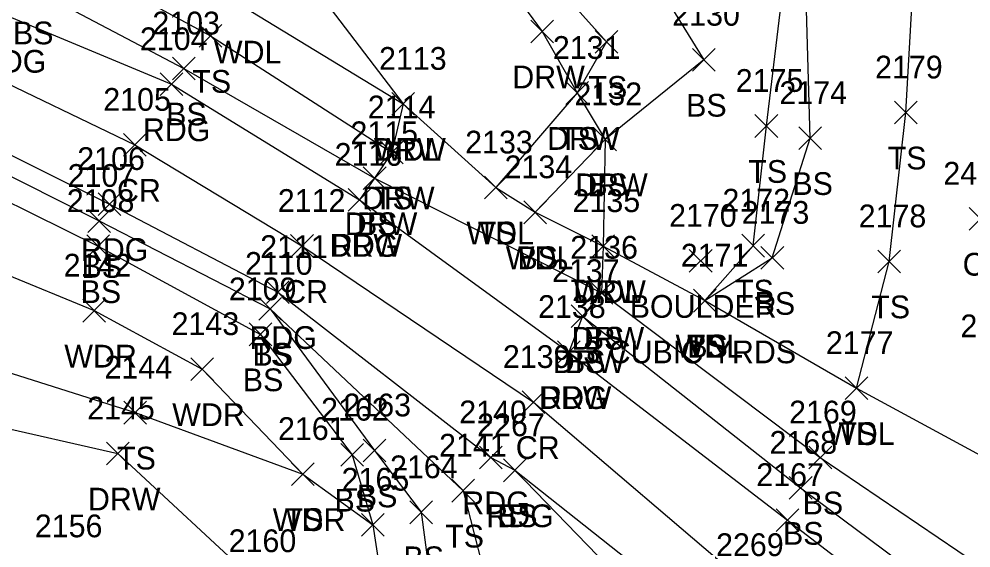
# Model space of a CAD drawing. Extents: x 1512665 to 1513714, y 110636 to 112816.
# Drawn here: x 1512914.5 to 1512998.3, y 110786.6 to 110833.1 of the extents above; entities that cross this region are included whole.
import ezdxf

# ---------------------------------------------------------------- set-up
doc = ezdxf.new("R2010")
doc.units = 0
for name, color, linetype in [('L_A', 7, 'Continuous'), ('L_C', 7, 'Continuous'), ('L_I', 7, 'Continuous'), ('L_TIC', 7, 'Continuous'), ('LAWA', 7, 'Continuous'), ('LELB', 7, 'Continuous'), ('P_A', 7, 'Continuous'), ('P_I', 7, 'Continuous'), ('P_TIC', 7, 'Continuous'), ('PEU', 7, 'Continuous'), ('PRC', 7, 'Continuous'), ('R_A', 7, 'Continuous'), ('R_I', 7, 'Continuous'), ('R_TIC', 7, 'Continuous'), ('RDW', 7, 'Continuous')]:
    doc.layers.add(name, color=color, linetype=linetype)

msp = doc.modelspace()

# ---------------------------------------------------------------- linework, layer by layer
at = {"layer": 'L_TIC'}
for points in [[(1512930.348, 110830.636), (1512932.348, 110832.636)], [(1512932.348, 110830.636), (1512930.348, 110832.636)], [(1512965.207, 110830.108), (1512967.207, 110832.108)], [(1512967.207, 110830.108), (1512965.207, 110832.108)], [(1512973.771, 110828.535), (1512975.771, 110830.535)], [(1512975.771, 110828.535), (1512973.771, 110830.535)], [(1512928.014, 110827.768), (1512930.014, 110829.768)], [(1512930.014, 110827.768), (1512928.014, 110829.768)], [(1512962.612, 110825.617), (1512964.612, 110827.617)], [(1512964.612, 110825.617), (1512962.612, 110827.617)], [(1512947.315, 110824.655), (1512949.315, 110826.655)], [(1512949.315, 110824.655), (1512947.315, 110826.655)], [(1512991.538, 110823.894), (1512993.538, 110825.894)], [(1512993.538, 110823.894), (1512991.538, 110825.894)], [(1512979.271, 110822.714), (1512981.271, 110824.714)], [(1512981.271, 110822.714), (1512979.271, 110824.714)], [(1512965.081, 110821.54), (1512967.081, 110823.54)], [(1512967.081, 110821.54), (1512965.081, 110823.54)], [(1512983.116, 110821.649), (1512985.116, 110823.649)], [(1512985.116, 110821.649), (1512983.116, 110823.649)], [(1512946.325, 110820.384), (1512948.325, 110822.384)], [(1512948.325, 110820.384), (1512946.325, 110822.384)], [(1512944.804, 110818.115), (1512946.804, 110820.115)], [(1512946.804, 110818.115), (1512944.804, 110820.115)], [(1512955.461, 110817.296), (1512957.461, 110819.296)], [(1512957.461, 110817.296), (1512955.461, 110819.296)], [(1512955.461, 110817.296), (1512957.461, 110819.296)], [(1512957.461, 110817.296), (1512955.461, 110819.296)], [(1512958.925, 110815.123), (1512960.925, 110817.123)], [(1512960.925, 110815.123), (1512958.925, 110817.123)], [(1512958.925, 110815.123), (1512960.925, 110817.123)], [(1512960.925, 110815.123), (1512958.925, 110817.123)], [(1512998.104, 110814.556), (1513000.104, 110816.556)], [(1513000.104, 110814.556), (1512998.104, 110816.556)], [(1512920.56, 110814.361), (1512922.56, 110816.361)], [(1512922.56, 110814.361), (1512920.56, 110816.361)], [(1512920.486, 110812.143), (1512922.486, 110814.143)], [(1512922.486, 110812.143), (1512920.486, 110814.143)], [(1512964.912, 110812.145), (1512966.912, 110814.145)], [(1512966.912, 110812.145), (1512964.912, 110814.145)], [(1512978.1, 110812.189), (1512980.1, 110814.189)], [(1512980.1, 110812.189), (1512978.1, 110814.189)], [(1512979.796, 110811.112), (1512981.796, 110813.112)], [(1512981.796, 110811.112), (1512979.796, 110813.112)], [(1512973.492, 110810.848), (1512975.492, 110812.848)], [(1512975.492, 110810.848), (1512973.492, 110812.848)], [(1512990.089, 110810.803), (1512992.089, 110812.803)], [(1512992.089, 110810.803), (1512990.089, 110812.803)], [(1512964.768, 110808.049), (1512966.768, 110810.049)], [(1512966.768, 110808.049), (1512964.768, 110810.049)], [(1512964.768, 110808.049), (1512966.768, 110810.049)], [(1512966.768, 110808.049), (1512964.768, 110810.049)], [(1512973.869, 110807.354), (1512975.869, 110809.354)], [(1512975.869, 110807.354), (1512973.869, 110809.354)], [(1512973.869, 110807.354), (1512975.869, 110809.354)], [(1512975.869, 110807.354), (1512973.869, 110809.354)], [(1512973.869, 110807.354), (1512975.869, 110809.354)], [(1512975.869, 110807.354), (1512973.869, 110809.354)], [(1512920.132, 110806.474), (1512922.132, 110808.474)], [(1512922.132, 110806.474), (1512920.132, 110808.474)], [(1512935.611, 110806.627), (1512937.611, 110808.627)], [(1512937.611, 110806.627), (1512935.611, 110808.627)], [(1512935.611, 110806.627), (1512937.611, 110808.627)], [(1512937.611, 110806.627), (1512935.611, 110808.627)], [(1512963.105, 110805.986), (1512965.105, 110807.986)], [(1512965.105, 110805.986), (1512963.105, 110807.986)], [(1512934.759, 110804.391), (1512936.759, 110806.391)], [(1512936.759, 110804.391), (1512934.759, 110806.391)], [(1512929.627, 110801.326), (1512931.627, 110803.326)], [(1512931.627, 110801.326), (1512929.627, 110803.326)], [(1512987.199, 110799.659), (1512989.199, 110801.659)], [(1512989.199, 110799.659), (1512987.199, 110801.659)], [(1512987.199, 110799.659), (1512989.199, 110801.659)], [(1512989.199, 110799.659), (1512987.199, 110801.659)], [(1512923.724, 110797.505), (1512925.724, 110799.505)], [(1512925.724, 110797.505), (1512923.724, 110799.505)], [(1512942.83, 110793.805), (1512944.83, 110795.805)], [(1512944.83, 110793.805), (1512942.83, 110795.805)], [(1512944.797, 110794.178), (1512946.797, 110796.178)], [(1512946.797, 110794.178), (1512944.797, 110796.178)], [(1512984.021, 110793.556), (1512986.021, 110795.556)], [(1512986.021, 110793.556), (1512984.021, 110795.556)], [(1512938.473, 110792.102), (1512940.473, 110794.102)], [(1512940.473, 110792.102), (1512938.473, 110794.102)], [(1512938.473, 110792.102), (1512940.473, 110794.102)], [(1512940.473, 110792.102), (1512938.473, 110794.102)], [(1512957.132, 110792.433), (1512959.132, 110794.433)], [(1512959.132, 110792.433), (1512957.132, 110794.433)], [(1512952.599, 110790.643), (1512954.599, 110792.643)], [(1512954.599, 110790.643), (1512952.599, 110792.643)], [(1512982.29, 110790.889), (1512984.29, 110792.889)], [(1512984.29, 110790.889), (1512982.29, 110792.889)], [(1512948.896, 110788.739), (1512950.896, 110790.739)], [(1512950.896, 110788.739), (1512948.896, 110790.739)], [(1512944.641, 110787.646), (1512946.641, 110789.646)], [(1512946.641, 110787.646), (1512944.641, 110789.646)], [(1512944.641, 110787.646), (1512946.641, 110789.646)], [(1512946.641, 110787.646), (1512944.641, 110789.646)]]:
    msp.add_lwpolyline(points, dxfattribs=at)
at = {"layer": 'LAWA'}
for points in [[(1512901.813, 110849.485), (1512918.081, 110842.567), (1512934.241, 110834.213), (1512948.315, 110825.655), (1512956.461, 110818.296), (1512959.925, 110816.123), (1512965.912, 110813.145), (1512974.869, 110808.354), (1512988.199, 110800.659), (1513000.869, 110793.798)], [(1512904.855, 110814.165), (1512921.132, 110807.474), (1512930.627, 110802.326), (1512939.473, 110793.102), (1512945.641, 110788.646), (1512946.819, 110780.951), (1512948.89, 110763.758), (1512946.989, 110749.434), (1512944.293, 110735.419), (1512940.962, 110714.938), (1512937.713, 110700.214), (1512950.792, 110688.786), (1512957.118, 110668.558), (1512971.82, 110659.404), (1512987.484, 110651.003), (1512993.751, 110649.548)]]:
    msp.add_lwpolyline(points, dxfattribs=at)
at = {"layer": 'LELB'}
for points in [[(1512867.091, 110954.959), (1512866.028, 110951.273), (1512867.897, 110945.243), (1512874.787, 110940.291), (1512895.063, 110927.72), (1512902.508, 110913.749), (1512928.484, 110897.044), (1512945.574, 110871.654), (1512953.444, 110855.33), (1512967.722, 110840.945), (1512974.771, 110829.535), (1512966.081, 110822.54), (1512959.925, 110816.123)], [(1512974.869, 110808.354), (1512980.796, 110812.112), (1512984.116, 110822.649), (1512983.374, 110849.355), (1512977.752, 110867.951), (1512973.997, 110889.114), (1512962.102, 110907.231), (1512950.876, 110925.19), (1512946.24, 110943.899), (1512941.465, 110952.585)], [(1512721.894, 110948.789), (1512722.497, 110942.68), (1512730.744, 110933.358), (1512741.905, 110924.629), (1512760.327, 110918.9), (1512788.256, 110897.799), (1512812.95, 110889.365), (1512823.675, 110884.08), (1512829.426, 110887.292), (1512828.602, 110891.881), (1512837.516, 110889.389), (1512842.176, 110886.401), (1512840.963, 110881.395), (1512842.492, 110877.537), (1512859.927, 110867.233), (1512885.327, 110852.839), (1512900.342, 110845.897), (1512916.833, 110839.511), (1512931.348, 110831.636), (1512947.325, 110821.384)], [(1512974.869, 110808.354), (1512979.1, 110813.189), (1512980.271, 110823.714), (1512983.374, 110849.355), (1512972.278, 110865.98), (1512966.818, 110886.579), (1512961.43, 110907.503), (1512945.779, 110917.038), (1512935.312, 110927.852), (1512933.427, 110939.129), (1512946.24, 110943.899), (1512951.888, 110947.414), (1512965.517, 110949.054), (1512967.677, 110937.89)], [(1512700.679, 110948.394), (1512702.883, 110937.76), (1512707.699, 110928.255), (1512715.725, 110919.825), (1512729.364, 110912.396), (1512733.114, 110910.816), (1512749.564, 110901.484), (1512765.39, 110894.395), (1512774.129, 110890.874), (1512779.73, 110888.581), (1512784.329, 110885.95), (1512807.054, 110874.728), (1512832.029, 110862.151), (1512849.873, 110852.9), (1512877.541, 110837.789), (1512892.067, 110830.383), (1512907.918, 110822.224), (1512921.56, 110815.361), (1512936.611, 110807.627), (1512945.797, 110795.178), (1512949.896, 110789.739), (1512950.992, 110781.568)], [(1512988.199, 110800.659), (1512991.089, 110811.803), (1512992.538, 110824.894), (1512993.987, 110850.149), (1512990.903, 110870.015), (1512992.225, 110882.229), (1512991.179, 110906.022), (1512982.382, 110920.046), (1512967.677, 110937.89)], [(1512899.968, 110905.165), (1512920.267, 110889.921), (1512938.022, 110866.04), (1512947.184, 110852.269), (1512966.207, 110831.108), (1512963.612, 110826.617), (1512956.461, 110818.296)], [(1512855.917, 110864.835), (1512884.122, 110850.682), (1512899.11, 110843.508), (1512915.531, 110835.895), (1512929.014, 110828.768), (1512945.804, 110819.115), (1512965.768, 110809.049)], [(1512832.029, 110862.151), (1512848.907, 110851.825), (1512876.28, 110836.219), (1512891.615, 110828.789), (1512906.871, 110820.366), (1512921.486, 110813.143), (1512935.759, 110805.391), (1512943.83, 110794.805), (1512945.641, 110788.646)], [(1512869.571, 110820.499), (1512887.31, 110807.394), (1512901.849, 110805.769), (1512924.724, 110798.505), (1512939.473, 110793.102)], [(1512965.768, 110809.049), (1512985.021, 110794.556), (1513002.316, 110782.838), (1513012.084, 110779.37), (1513025.948, 110772.452), (1513031.778, 110776.166)], [(1512936.611, 110807.627), (1512953.599, 110791.643), (1512956.195, 110781.418), (1512968.46, 110770.893), (1512974.971, 110752.732), (1512977.394, 110741.958), (1512974.26, 110721.428)], [(1512964.105, 110806.986), (1512983.29, 110791.889), (1512999.323, 110779.951), (1513012.212, 110774.48), (1513024.663, 110768.294), (1513032.242, 110771.906), (1513035.849, 110774.486)], [(1512958.132, 110793.433), (1512973.652, 110777.453), (1512981.607, 110755.641), (1512996.294, 110746.637), (1513006.992, 110744.376), (1513016.029, 110743.308), (1513026.953, 110745.673), (1513036.177, 110748.289)]]:
    msp.add_lwpolyline(points, dxfattribs=at)
at = {"layer": 'P_TIC'}
for points in [[(1512926.92, 110826.382), (1512928.92, 110828.382)], [(1512928.92, 110826.382), (1512926.92, 110828.382)], [(1512923.695, 110821.052), (1512925.695, 110823.052)], [(1512925.695, 110821.052), (1512923.695, 110823.052)], [(1512943.462, 110816.212), (1512945.462, 110818.212)], [(1512945.462, 110816.212), (1512943.462, 110818.212)], [(1512921.462, 110815.848), (1512923.462, 110817.848)], [(1512923.462, 110815.848), (1512921.462, 110817.848)], [(1512938.408, 110812.161), (1512940.408, 110814.161)], [(1512940.408, 110812.161), (1512938.408, 110814.161)], [(1512936.29, 110808.107), (1512938.29, 110810.107)], [(1512938.29, 110808.107), (1512936.29, 110810.107)], [(1512961.879, 110802.833), (1512963.879, 110804.833)], [(1512963.879, 110802.833), (1512961.879, 110804.833)], [(1512958.787, 110798.435), (1512960.787, 110800.435)], [(1512960.787, 110798.435), (1512958.787, 110800.435)], [(1512955.028, 110793.571), (1512957.028, 110795.571)], [(1512957.028, 110793.571), (1512955.028, 110795.571)], [(1512957.132, 110792.433), (1512959.132, 110794.433)], [(1512959.132, 110792.433), (1512957.132, 110794.433)], [(1512981.126, 110788.052), (1512983.126, 110790.052)], [(1512983.126, 110788.052), (1512981.126, 110790.052)]]:
    msp.add_lwpolyline(points, dxfattribs=at)
at = {"layer": 'PEU'}
for points in [[(1512701.918, 111049.687), (1512700.272, 111027.695), (1512701.575, 110993.777), (1512707.634, 110973.739), (1512708.973, 110956.468), (1512713.567, 110946.899), (1512719.219, 110936.541), (1512726.895, 110929.376), (1512741.614, 110919.596), (1512758.159, 110912.379), (1512787.354, 110896.005), (1512813.053, 110887.984), (1512838.367, 110874.777), (1512855.917, 110864.835), (1512882.817, 110848.349), (1512898.24, 110841.366), (1512913.486, 110833.402), (1512927.92, 110827.382), (1512944.462, 110817.212), (1512962.879, 110803.833), (1512982.126, 110789.052), (1512997.253, 110777.445), (1513011.324, 110770.561), (1513024.004, 110765.991)], [(1512908.545, 110823.763), (1512922.462, 110816.848), (1512937.29, 110809.107), (1512956.028, 110794.571), (1512958.132, 110793.433), (1512975.798, 110779.469), (1512988.794, 110763.009), (1513002.098, 110756.133), (1513012.974, 110751.731), (1513022.336, 110752.03), (1513042.715, 110756.056), (1513045.977, 110758.546), (1513043.773, 110764.486), (1513041.72, 110768.766), (1513036.521, 110767.718), (1513024.004, 110765.991)]]:
    msp.add_lwpolyline(points, dxfattribs=at)
at = {"layer": 'PRC'}
msp.add_lwpolyline([(1512910.919, 110828.697), (1512924.695, 110822.052), (1512939.408, 110813.161), (1512959.787, 110799.435), (1512979.162, 110782.894), (1512994.968, 110767.907), (1513005.499, 110762.392), (1513013.716, 110758.318), (1513024.25, 110758.228), (1513034.128, 110760.688), (1513043.773, 110764.486)], dxfattribs=at)
at = {"layer": 'R_TIC'}
for points in [[(1512959.543, 110831.025), (1512961.543, 110833.025)], [(1512961.543, 110831.025), (1512959.543, 110833.025)], [(1512962.612, 110825.617), (1512964.612, 110827.617)], [(1512964.612, 110825.617), (1512962.612, 110827.617)], [(1512947.315, 110824.655), (1512949.315, 110826.655)], [(1512949.315, 110824.655), (1512947.315, 110826.655)], [(1512965.081, 110821.54), (1512967.081, 110823.54)], [(1512967.081, 110821.54), (1512965.081, 110823.54)], [(1512946.325, 110820.384), (1512948.325, 110822.384)], [(1512948.325, 110820.384), (1512946.325, 110822.384)], [(1512944.804, 110818.115), (1512946.804, 110820.115)], [(1512946.804, 110818.115), (1512944.804, 110820.115)], [(1512943.462, 110816.212), (1512945.462, 110818.212)], [(1512945.462, 110816.212), (1512943.462, 110818.212)], [(1512964.912, 110812.145), (1512966.912, 110814.145)], [(1512966.912, 110812.145), (1512964.912, 110814.145)], [(1512964.768, 110808.049), (1512966.768, 110810.049)], [(1512966.768, 110808.049), (1512964.768, 110810.049)], [(1512963.105, 110805.986), (1512965.105, 110807.986)], [(1512965.105, 110805.986), (1512963.105, 110807.986)], [(1512961.879, 110802.833), (1512963.879, 110804.833)], [(1512963.879, 110802.833), (1512961.879, 110804.833)], [(1512922.203, 110793.904), (1512924.203, 110795.904)], [(1512924.203, 110793.904), (1512922.203, 110795.904)]]:
    msp.add_lwpolyline(points, dxfattribs=at)
at = {"layer": 'RDW'}
for points in [[(1512846.807, 110959.221), (1512852.941, 110946.592), (1512861.965, 110937.336), (1512883.211, 110922.012), (1512899.968, 110905.165), (1512926.485, 110873.446), (1512935.332, 110863.205), (1512946.848, 110850.628), (1512960.543, 110832.025), (1512963.612, 110826.617), (1512966.081, 110822.54), (1512965.912, 110813.145), (1512965.768, 110809.049), (1512964.105, 110806.986), (1512962.879, 110803.833)], [(1512831.666, 110950.261), (1512839.34, 110942.793), (1512851.809, 110930.104), (1512872.871, 110913.575), (1512891.99, 110892.675), (1512913.156, 110874.506), (1512928.573, 110854.542), (1512938.494, 110838.55), (1512948.315, 110825.655), (1512947.325, 110821.384), (1512945.804, 110819.115), (1512944.462, 110817.212)], [(1512900.459, 110800.085), (1512923.203, 110794.904), (1512935.784, 110783.238), (1512946.819, 110780.951), (1512959.698, 110764.789), (1512961.676, 110750.74), (1512964.35, 110737.826), (1512956.004, 110719.217), (1512960.653, 110706.287), (1512964.16, 110695.737), (1512971.265, 110683.804), (1512977.643, 110679.977), (1512982.193, 110667.902), (1512995.78, 110663.608), (1513006.943, 110650.515)]]:
    msp.add_lwpolyline(points, dxfattribs=at)

# ---------------------------------------------------------------- texts
at = {"layer": 'L_A'}
for s, p in [('BS', (1512913.972, 110830.895)), ('WDL', (1512931.658, 110829.213)), ('TS', (1512929.757, 110826.636)), ('TS', (1512964.616, 110826.108)), ('BS', (1512973.212, 110824.535)), ('BS', (1512927.455, 110823.768)), ('TS', (1512962.021, 110821.617)), ('WDL', (1512945.732, 110820.655)), ('TS', (1512990.947, 110819.894)), ('TS', (1512978.68, 110818.714)), ('BS', (1512964.522, 110817.54)), ('BS', (1512982.557, 110817.649)), ('TS', (1512945.734, 110816.384)), ('BS', (1512944.245, 110814.115)), ('WDL', (1512953.878, 110813.296)), ('TS', (1512954.87, 110813.296)), ('WDL', (1512957.343, 110811.123)), ('BS', (1512958.366, 110811.123)), ('BS', (1512920.001, 110810.361)), ('CS', (1512997.545, 110810.556)), ('BS', (1512919.927, 110808.143)), ('WDL', (1512963.329, 110808.145)), ('TS', (1512977.51, 110808.189)), ('BS', (1512979.237, 110807.112)), ('BOULDER', (1512968.247, 110806.848)), ('TS', (1512989.499, 110806.803)), ('BS', (1512964.209, 110804.049)), ('BS', (1512964.209, 110804.049)), ('WDL', (1512972.286, 110803.354)), ('TS', (1512973.278, 110803.354)), ('BS', (1512973.31, 110803.354)), ('WDR', (1512918.495, 110802.474)), ('TS', (1512935.02, 110802.627)), ('BS', (1512935.052, 110802.627)), ('BS', (1512962.546, 110801.986)), ('BS', (1512934.2, 110800.391)), ('WDR', (1512927.99, 110797.326)), ('WDL', (1512985.616, 110795.659)), ('TS', (1512986.608, 110795.659)), ('TS', (1512923.133, 110793.505)), ('BS', (1512944.238, 110790.178)), ('BS', (1512942.271, 110789.805)), ('BS', (1512983.462, 110789.556)), ('BS', (1512956.573, 110788.433)), ('WDR', (1512936.835, 110788.102)), ('TS', (1512937.882, 110788.102)), ('BS', (1512981.731, 110786.889)), ('TS', (1512952.008, 110786.643)), ('BS', (1512948.337, 110784.739))]:
    msp.add_text(s, height=2, dxfattribs=at).set_placement(p)
at = {"layer": 'L_C'}
msp.add_text('3 CUBIC YRDS', height=2, dxfattribs=at).set_placement((1512964.161, 110802.848))
at = {"layer": 'L_I'}
for s, p in [('2130', (1512971.991, 110832.535)), ('2103', (1512926.243, 110831.768)), ('2131', (1512961.486, 110829.617)), ('2113', (1512946.189, 110828.655)), ('2179', (1512989.837, 110827.894)), ('2175', (1512977.578, 110826.714)), ('2132', (1512963.388, 110825.54)), ('2174', (1512981.423, 110825.649)), ('2114', (1512945.199, 110824.384)), ('2115', (1512943.678, 110822.115)), ('2133', (1512953.768, 110821.296)), ('2133', (1512953.768, 110821.296)), ('2134', (1512957.233, 110819.123)), ('2134', (1512957.233, 110819.123)), ('2107', (1512918.788, 110818.361)), ('2482', (1512995.844, 110818.556)), ('2108', (1512918.714, 110816.143)), ('2135', (1512963.219, 110816.145)), ('2172', (1512976.408, 110816.189)), ('2170', (1512971.712, 110814.848)), ('2173', (1512978.103, 110815.112)), ('2178', (1512988.396, 110814.803)), ('2136', (1512963.02, 110812.049)), ('2136', (1512963.02, 110812.049)), ('2171', (1512972.743, 110811.354)), ('2171', (1512972.743, 110811.354)), ('2171', (1512972.743, 110811.354)), ('2142', (1512918.44, 110810.474)), ('2110', (1512934.398, 110810.627)), ('2110', (1512934.398, 110810.627)), ('2137', (1512961.412, 110809.986)), ('2109', (1512932.979, 110808.391)), ('2143', (1512927.934, 110805.326)), ('2481', (1512997.35, 110805.133)), ('2481', (1512997.35, 110805.133)), ('2177', (1512985.506, 110803.659)), ('2177', (1512985.506, 110803.659)), ('2144', (1512922.031, 110801.505)), ('2162', (1512941.09, 110797.805)), ('2163', (1512943.057, 110798.178)), ('2169', (1512982.273, 110797.556)), ('2161', (1512937.299, 110796.102)), ('2161', (1512937.299, 110796.102)), ('2267', (1512954.825, 110796.433)), ('2141', (1512951.473, 110794.643)), ('2168', (1512980.55, 110794.889)), ('2164', (1512947.156, 110792.739)), ('2165', (1512942.9, 110791.646)), ('2165', (1512942.9, 110791.646))]:
    msp.add_text(s, height=2, dxfattribs=at).set_placement(p)
at = {"layer": 'P_A'}
for s, p in [('RDG', (1512910.974, 110828.402)), ('RDG', (1512925.409, 110822.382)), ('CR', (1512923.129, 110817.052)), ('RDG', (1512941.951, 110812.212)), ('RDG', (1512919.95, 110811.848)), ('CR', (1512937.841, 110808.161)), ('RDG', (1512934.779, 110804.107)), ('RDG', (1512960.367, 110798.833)), ('CR', (1512958.22, 110794.435)), ('RDG', (1512953.517, 110789.571)), ('RDG', (1512955.62, 110788.433))]:
    msp.add_text(s, height=2, dxfattribs=at).set_placement(p)
at = {"layer": 'P_I'}
for s, p in [('2104', (1512925.149, 110830.382)), ('2105', (1512921.924, 110825.052)), ('2106', (1512919.635, 110819.848)), ('2116', (1512942.281, 110820.212)), ('2112', (1512937.282, 110816.161)), ('2111', (1512935.731, 110812.107)), ('2138', (1512960.186, 110806.833)), ('2139', (1512957.086, 110802.435)), ('2140', (1512953.249, 110797.571)), ('2267', (1512954.825, 110796.433)), ('2167', (1512979.386, 110792.052)), ('2269', (1512975.847, 110785.894))]:
    msp.add_text(s, height=2, dxfattribs=at).set_placement(p)
at = {"layer": 'R_A'}
for p in [(1512957.914, 110827.025), (1512960.982, 110821.617), (1512945.685, 110820.655), (1512963.451, 110817.54), (1512944.695, 110816.384), (1512943.174, 110814.115), (1512941.833, 110812.212), (1512963.282, 110808.145), (1512963.138, 110804.049), (1512961.475, 110801.986), (1512960.249, 110798.833), (1512920.573, 110789.904)]:
    msp.add_text('DRW', height=2, dxfattribs=at).set_placement(p)
at = {"layer": 'R_I'}
for s, p in [('2131', (1512961.486, 110829.617)), ('2113', (1512946.189, 110828.655)), ('2132', (1512963.388, 110825.54)), ('2114', (1512945.199, 110824.384)), ('2115', (1512943.678, 110822.115)), ('2116', (1512942.281, 110820.212)), ('2135', (1512963.219, 110816.145)), ('2136', (1512963.02, 110812.049)), ('2137', (1512961.412, 110809.986)), ('2138', (1512960.186, 110806.833)), ('2145', (1512920.51, 110797.904)), ('2156', (1512915.901, 110787.546)), ('2160', (1512932.957, 110786.238))]:
    msp.add_text(s, height=2, dxfattribs=at).set_placement(p)

doc.saveas('drawing.dxf')
